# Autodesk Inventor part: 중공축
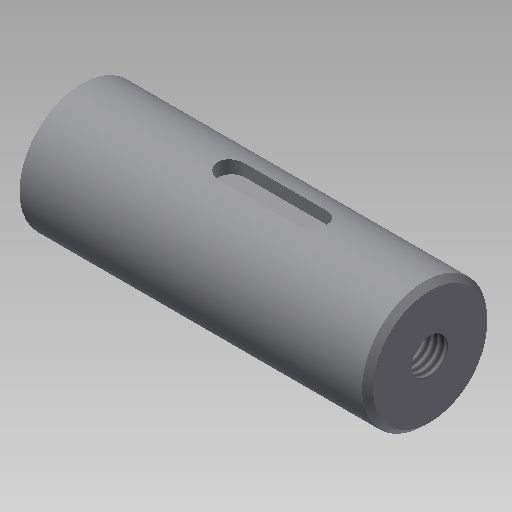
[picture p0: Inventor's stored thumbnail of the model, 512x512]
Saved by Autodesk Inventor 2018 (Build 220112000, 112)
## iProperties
Created: 2019-10
Part Number: 중공축
Material: 강철, 탄소
Document SubType Name: Modeling
Designer: mduedu
Density: 1 g/cm^3
Appearance: 기본값
Author: mduedu
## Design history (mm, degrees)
sketch "스케치1"
  geometry: L1 (0, 0)-(64, 0); L2 (64, 0)-(64, 11.5); L3 (64, 11.5)-(0, 11.5); L4 (0, 11.5)-(0, 0)
  constraints: 8 end point, 2 parallel, 1 horizontal, 1 perpendicular
  dimensions: "d0" = 64 distance of L2.end L3.end; "d2" = 23 diameter of L3 L1
revolve "회전1" sketch "스케치1" stored, may be unused: angle "d3" = 90 deg
hole "구멍1" diameter "d6" = 6.647; stored, may be unused: countersink angle "d10" = 90 deg, drill point angle "d12" = 118 deg; dims "d4" = 10, "d5" = 10, "d7" = 6, "d8" = 4, "d9" = 2, "d11" = 8
hole "구멍2" diameter "d15" = 13; stored, may be unused: countersink angle "d19" = 90 deg, drill point angle "d21" = 0 deg; dims "d13" = 10, "d14" = 10, "d16" = 6, "d17" = 15, "d18" = 20, "d20" = 32
sketch "스케치2"
  geometry: L1 (20, -7.5)-(20, -6.5) reference; L2 (20, -6.5)-(52, -6.5) reference; L3 (52, -6.5)-(52, -3.324) reference; L4 (52, -3.324)-(64, -3.324) reference; L5 (64, -3.324)-(64, -11.5) reference; L6 (64, -11.5)-(0, -11.5) reference; L7 (0, -11.5)-(0, -7.5) reference; L8 (0, -7.5)-(20, -7.5) reference; L9 (20, 6.5)-(20, 7.5) reference; L10 (20, 7.5)-(0, 7.5) reference; L11 (0, 7.5)-(0, 11.5) reference; L12 (0, 11.5)-(64, 11.5) reference; L13 (64, 11.5)-(64, 3.324) reference; L14 (64, 3.324)-(52, 3.324) reference; L15 (52, 3.324)-(52, 6.5) reference; L16 (52, 6.5)-(20, 6.5) reference; L17 (25, 11.5)-(45, 11.5); L18 (45, 11.5)-(45, 9); L19 (45, 9)-(25, 9); L20 (25, 9)-(25, 11.5); 1 further point
  constraints: 8 end point, 2 parallel, 1 horizontal, 1 perpendicular, 1 point on line
  dimensions: "d22" = 20 distance of L17.start L17.end; "d24" = 25 distance between parallel lines of L20 L11; "d25" = 2.5 distance of L17.end L18.end
extrude "돌출1" cut sketch "스케치2" stored distance "d26" = 5; taper "d27" = 0 deg
fillet "모깎기1"
fillet "모깎기2"
sketch "스케치3"
  geometry: 3 further points
  constraints: 2 vertical alignment, 1 other
hole "구멍3" sketch "스케치3" at (0, 7.5) diameter "d28" = 2.459; stored, may be unused: countersink angle "d32" = 90 deg, drill point angle "d34" = 118 deg; dims "d29" = 6, "d30" = 4, "d31" = 2, "d33" = 8
chamfer "모따기1" distance "d35" = 1; stored, may be unused: second distance "d36" = 2, angle "d37" = 45 deg
node "솔리드1"
node "절단 모서리 투영1"
